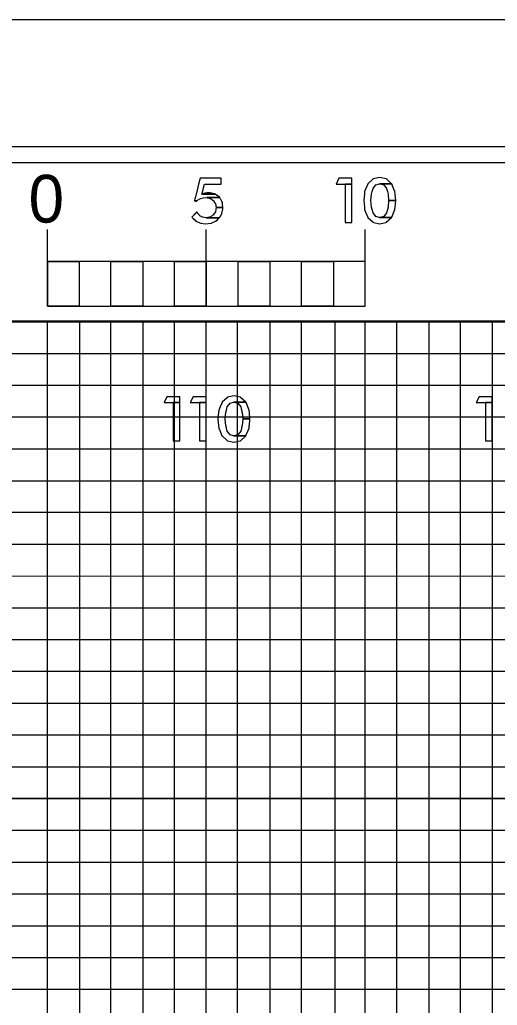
# Model space of a CAD drawing. Extents: x -13 to 323, y -5 to 1431.
# Drawn here: x 264.13 to 279.16, y 1283.5 to 1314.5 of the extents above; entities that cross this region are included whole.
import ezdxf

# ---------------------------------------------------------------- set-up
doc = ezdxf.new("R2010")
doc.units = 0
for name, color, linetype in [('Prop XS Bar Scale Labels', 7, 'Continuous'), ('Prop XS Offset Labels', 7, 'Continuous'), ('Sheet Cross Section CELL', 7, 'Continuous'), ('Sheet Cross Section Grid Major CELL', 7, 'Continuous'), ('Sheet Cross Section Grid Middle CELL', 7, 'Continuous'), ('Sheet Cross Section Grid Minor 1 CELL', 7, 'Continuous'), ('Sheet Cross Section Grid Minor 2 CELL', 7, 'Continuous'), ('Sheet Cross Section Scale CELL', 7, 'Continuous'), ('Sheet Cutting Line CELL', 7, 'Continuous'), ('Sheet DOT Grid CELL', 7, 'Continuous'), ('Sheet Plot Border Inside CELL', 7, 'Continuous'), ('Sheet Plot Border Outside CELL', 7, 'Continuous')]:
    doc.layers.add(name, color=color, linetype=linetype)

msp = doc.modelspace()

# ---------------------------------------------------------------- linework, layer by layer
at = {"layer": 'Prop XS Bar Scale Labels'}
for points in [[(269.63, 1308.81), (269.627, 1308.798), (269.698, 1308.798), (269.711, 1308.81), (269.727, 1308.824), (269.798, 1308.867), (269.83, 1308.877), (269.9, 1308.899), (270.014, 1308.905), (270.422, 1308.905), (270.414, 1308.92), (270.28, 1309.015), (269.858, 1309.015), (269.861, 1309.028), (269.861, 1309.028), (269.866, 1309.048), (269.941, 1309.326), (270.466, 1309.326), (270.466, 1309.511), (269.803, 1309.511), (269.757, 1309.326), (269.689, 1309.048), (269.684, 1309.028), (269.681, 1309.015), (269.658, 1308.92), (269.654, 1308.905), (269.652, 1308.899), (269.647, 1308.877), (269.644, 1308.867), (269.634, 1308.824)], [(274.174, 1309.511), (274.085, 1309.329), (274.583, 1309.329), (274.583, 1309.511)], [(275.258, 1308.125), (275.457, 1308.084), (275.652, 1308.125), (275.663, 1308.127), (275.828, 1308.279), (275.454, 1308.279), (275.445, 1308.281), (275.44, 1308.283), (275.335, 1308.312), (275.248, 1308.425), (275.248, 1308.426), (275.248, 1308.426), (275.22, 1308.527), (275.22, 1308.529), (275.2, 1308.602), (275.198, 1308.606), (275.181, 1308.809), (275.181, 1308.811), (275.181, 1308.813), (275.198, 1309.015), (275.219, 1309.092), (275.22, 1309.094), (275.246, 1309.192), (275.247, 1309.195), (275.335, 1309.31), (275.448, 1309.339), (275.452, 1309.34), (275.462, 1309.343), (275.832, 1309.343), (275.669, 1309.492), (275.66, 1309.494), (275.46, 1309.538), (275.46, 1309.538), (275.252, 1309.494), (275.25, 1309.492), (275.088, 1309.343), (275.085, 1309.34), (275.084, 1309.339), (275.072, 1309.31), (275.025, 1309.195), (275.024, 1309.192), (274.983, 1309.094), (274.983, 1309.092), (274.975, 1309.015), (274.954, 1308.813), (274.953, 1308.811), (274.954, 1308.809), (274.974, 1308.606), (274.974, 1308.602), (274.982, 1308.529), (274.982, 1308.527), (275.023, 1308.426), (275.024, 1308.425), (275.07, 1308.312), (275.082, 1308.283), (275.082, 1308.281), (275.085, 1308.279), (275.255, 1308.127)], [(274.374, 1309.329), (274.374, 1308.12), (274.583, 1308.12), (274.583, 1309.329)], [(275.719, 1309.015), (275.735, 1308.813), (275.962, 1308.813), (275.942, 1309.015), (275.935, 1309.092), (275.934, 1309.094), (275.934, 1309.094), (275.895, 1309.192), (275.895, 1309.192), (275.893, 1309.195), (275.848, 1309.31), (275.847, 1309.31), (275.835, 1309.339), (275.835, 1309.34), (275.832, 1309.343), (275.462, 1309.343), (275.472, 1309.34), (275.475, 1309.339), (275.582, 1309.31), (275.669, 1309.195), (275.672, 1309.192), (275.698, 1309.094), (275.698, 1309.092)], [(269.895, 1309.028), (269.858, 1309.015), (270.28, 1309.015), (270.262, 1309.028), (270.164, 1309.048), (269.953, 1309.048)], [(270.091, 1309.062), (269.953, 1309.048), (270.164, 1309.048), (270.091, 1309.062)], [(270.286, 1308.711), (270.308, 1308.591), (270.521, 1308.591), (270.51, 1308.711), (270.51, 1308.711), (270.507, 1308.751), (270.487, 1308.786), (270.481, 1308.798), (270.475, 1308.81), (270.467, 1308.824), (270.443, 1308.867), (270.438, 1308.877), (270.426, 1308.899), (270.422, 1308.905), (270.014, 1308.905), (270.041, 1308.899), (270.132, 1308.877), (270.146, 1308.867), (270.206, 1308.824), (270.227, 1308.81), (270.234, 1308.798), (270.241, 1308.786), (270.262, 1308.751)], [(269.627, 1308.798), (269.685, 1308.786), (269.698, 1308.798)], [(270.103, 1308.288), (269.996, 1308.269), (270.408, 1308.269), (270.423, 1308.288), (270.424, 1308.289), (270.425, 1308.29), (270.425, 1308.29), (270.462, 1308.336), (270.471, 1308.347), (270.473, 1308.353), (270.487, 1308.405), (270.502, 1308.46), (270.525, 1308.544), (270.521, 1308.591), (270.308, 1308.591), (270.3, 1308.544), (270.286, 1308.46), (270.25, 1308.405), (270.217, 1308.353), (270.207, 1308.347), (270.19, 1308.336), (270.116, 1308.29), (270.108, 1308.289)], [(275.465, 1308.281), (275.454, 1308.279), (275.828, 1308.279), (275.831, 1308.281), (275.833, 1308.283), (275.845, 1308.312), (275.892, 1308.425), (275.892, 1308.426), (275.934, 1308.527), (275.935, 1308.529), (275.942, 1308.602), (275.942, 1308.606), (275.962, 1308.809), (275.963, 1308.811), (275.962, 1308.813), (275.735, 1308.813), (275.735, 1308.811), (275.735, 1308.809), (275.719, 1308.606), (275.718, 1308.602), (275.699, 1308.529), (275.698, 1308.527), (275.671, 1308.426), (275.67, 1308.425), (275.582, 1308.312), (275.47, 1308.283)], [(269.829, 1308.103), (269.965, 1308.084), (270.163, 1308.103), (270.171, 1308.107), (270.294, 1308.167), (270.294, 1308.167), (270.344, 1308.191), (270.388, 1308.245), (270.408, 1308.269), (269.996, 1308.269), (269.887, 1308.288), (269.885, 1308.289), (269.882, 1308.29), (269.799, 1308.336), (269.789, 1308.347), (269.783, 1308.353), (269.783, 1308.353), (269.733, 1308.405), (269.7, 1308.455), (269.7, 1308.455), (269.655, 1308.405), (269.608, 1308.353), (269.602, 1308.347), (269.593, 1308.336), (269.551, 1308.29), (269.55, 1308.289), (269.551, 1308.288), (269.566, 1308.269), (269.585, 1308.245), (269.649, 1308.191), (269.677, 1308.167), (269.801, 1308.107)]]:
    msp.add_lwpolyline(points, close=True, dxfattribs=at)
at = {"layer": 'Prop XS Offset Labels'}
for points in [[(268.76, 1302.641), (268.671, 1302.459), (269.17, 1302.459), (269.17, 1302.641)], [(269.587, 1302.641), (269.498, 1302.459), (269.997, 1302.459), (269.997, 1302.641)], [(270.672, 1301.255), (270.871, 1301.214), (271.066, 1301.255), (271.077, 1301.257), (271.242, 1301.409), (270.868, 1301.409), (270.858, 1301.411), (270.853, 1301.413), (270.749, 1301.442), (270.662, 1301.555), (270.661, 1301.556), (270.661, 1301.556), (270.634, 1301.657), (270.633, 1301.659), (270.613, 1301.732), (270.612, 1301.736), (270.594, 1301.939), (270.594, 1301.941), (270.595, 1301.943), (270.612, 1302.145), (270.633, 1302.222), (270.633, 1302.224), (270.66, 1302.322), (270.661, 1302.325), (270.749, 1302.44), (270.862, 1302.469), (270.865, 1302.47), (270.876, 1302.473), (271.246, 1302.473), (271.082, 1302.622), (271.074, 1302.624), (270.873, 1302.668), (270.873, 1302.668), (270.665, 1302.624), (270.663, 1302.622), (270.502, 1302.473), (270.499, 1302.47), (270.498, 1302.469), (270.486, 1302.44), (270.439, 1302.325), (270.437, 1302.322), (270.397, 1302.224), (270.397, 1302.222), (270.389, 1302.145), (270.367, 1301.943), (270.367, 1301.941), (270.367, 1301.939), (270.387, 1301.736), (270.388, 1301.732), (270.395, 1301.659), (270.396, 1301.657), (270.437, 1301.556), (270.437, 1301.555), (270.483, 1301.442), (270.495, 1301.413), (270.496, 1301.411), (270.499, 1301.409), (270.669, 1301.257)], [(278.581, 1302.641), (278.492, 1302.459), (278.99, 1302.459), (278.99, 1302.641)], [(268.961, 1302.459), (268.961, 1301.25), (269.17, 1301.25), (269.17, 1302.459)], [(269.788, 1302.459), (269.788, 1301.25), (269.997, 1301.25), (269.997, 1302.459)], [(271.132, 1302.145), (271.149, 1301.943), (271.376, 1301.943), (271.356, 1302.145), (271.349, 1302.222), (271.348, 1302.224), (271.348, 1302.224), (271.308, 1302.322), (271.308, 1302.322), (271.307, 1302.325), (271.261, 1302.44), (271.261, 1302.44), (271.249, 1302.469), (271.249, 1302.47), (271.246, 1302.473), (270.876, 1302.473), (270.885, 1302.47), (270.889, 1302.469), (270.995, 1302.44), (271.083, 1302.325), (271.085, 1302.322), (271.111, 1302.224), (271.112, 1302.222)], [(278.781, 1302.459), (278.781, 1301.25), (278.99, 1301.25), (278.99, 1302.459)], [(270.878, 1301.411), (270.868, 1301.409), (271.242, 1301.409), (271.245, 1301.411), (271.247, 1301.413), (271.259, 1301.442), (271.305, 1301.555), (271.306, 1301.556), (271.348, 1301.657), (271.348, 1301.659), (271.355, 1301.732), (271.356, 1301.736), (271.376, 1301.939), (271.376, 1301.941), (271.376, 1301.943), (271.149, 1301.943), (271.149, 1301.941), (271.148, 1301.939), (271.132, 1301.736), (271.132, 1301.732), (271.112, 1301.659), (271.112, 1301.657), (271.085, 1301.556), (271.084, 1301.555), (270.995, 1301.442), (270.883, 1301.413)]]:
    msp.add_lwpolyline(points, close=True, dxfattribs=at)
at = {"layer": 'Sheet Cross Section CELL'}
for points in [[(320, 1310), (0, 1310), (0, 1100), (320, 1100)], [(280, 1310), (260, 1310), (260, 1305.03), (280, 1305.03)]]:
    msp.add_lwpolyline(points, close=True, dxfattribs=at)
at = {"layer": 'Sheet Cross Section Grid Major CELL'}
msp.add_line((270, 1100), (270, 1305), dxfattribs=at)
msp.add_lwpolyline([(0, 1300), (320, 1300), (320, 1290), (0, 1290)], dxfattribs=at)
at = {"layer": 'Sheet Cross Section Grid Middle CELL'}
for points in [[(255, 1100), (255, 1310), (259.93, 1310), (260, 1310), (260, 1305), (264.99, 1305), (264.99, 1100)], [(0, 1305), (275, 1305)], [(275, 1100), (275, 1305), (285, 1305), (285, 1100)], [(0, 1285), (320, 1285), (320, 1295), (0, 1295)]]:
    msp.add_lwpolyline(points, dxfattribs=at)
at = {"layer": 'Sheet Cross Section Grid Minor 1 CELL'}
msp.add_line((0, 1304), (320, 1304), dxfattribs=at)
for points in [[(0, 1303), (270, 1303), (320, 1303), (320, 1302), (0, 1302)], [(0, 1301), (320, 1301), (320, 1299), (0, 1299)], [(0, 1298), (320, 1298), (320, 1297), (0, 1296.98)], [(0, 1296), (320, 1296), (320, 1294), (0, 1294)], [(0, 1293), (320, 1293), (320, 1292), (0, 1292)], [(0, 1291), (320, 1291), (320, 1289), (0, 1289)], [(0, 1288), (320, 1288), (320, 1287), (0, 1287)], [(0, 1286), (320, 1286), (320, 1284), (0, 1284)]]:
    msp.add_lwpolyline(points, dxfattribs=at)
at = {"layer": 'Sheet Cross Section Grid Minor 2 CELL'}
for p, q in [((267, 1305), (266.01, 1305)), ((266.01, 1305), (266.01, 1100)), ((267, 1100), (267, 1305)), ((269, 1305), (268, 1305)), ((268, 1305), (268, 1100)), ((269, 1100), (269, 1305))]:
    msp.add_line(p, q, dxfattribs=at)
for points in [[(270, 1100), (270.98, 1100), (270.98, 1305), (272, 1305), (272, 1100)], [(272, 1100), (273, 1100), (273, 1305), (274.05, 1305), (274.05, 1100)], [(275, 1100), (276, 1100), (276, 1305), (277, 1305), (277, 1100)], [(277, 1100), (278, 1100), (278, 1305), (279, 1305), (279, 1100)]]:
    msp.add_lwpolyline(points, dxfattribs=at)
at = {"layer": 'Sheet Cross Section Scale CELL'}
for p, q in [((265, 1305.49), (265, 1307.9)), ((265, 1306.9), (265, 1307.9)), ((270, 1305.49), (270, 1307.9)), ((275, 1305.49), (275, 1307.9)), ((275, 1306.9), (275, 1307.9))]:
    msp.add_line(p, q, dxfattribs=at)
for points in [[(275, 1306.9), (265, 1306.9), (265, 1305.49), (275, 1305.49)], [(265, 1306.9), (266, 1306.9), (266, 1305.49), (265, 1305.49)], [(267, 1306.9), (268, 1306.9), (268, 1305.49), (267, 1305.49)], [(269, 1306.9), (270, 1306.9), (270, 1305.49), (269, 1305.49)], [(271, 1306.9), (272, 1306.9), (272, 1305.49), (271, 1305.49)], [(273, 1306.9), (274, 1306.9), (274, 1305.49), (273, 1305.49)]]:
    msp.add_lwpolyline(points, close=True, dxfattribs=at)
at = {"layer": 'Sheet Cutting Line CELL'}
msp.add_line((323.3, 1314.5), (-13.4, 1314.5), dxfattribs=at)
at = {"layer": 'Sheet DOT Grid CELL'}
for p, q in [((270, 1100), (270, 1304.687)), ((0, 1300), (320, 1300)), ((0, 1290), (320, 1290))]:
    msp.add_line(p, q, dxfattribs=at)
at = {"layer": 'Sheet Plot Border Inside CELL'}
msp.add_lwpolyline([(-10.8, 1099.5), (322.4, 1099.5), (322.4, 1310.5), (-10.8, 1310.5)], close=True, dxfattribs=at)
at = {"layer": 'Sheet Plot Border Outside CELL'}
msp.add_lwpolyline([(-13.4, 1095.5), (323.3, 1095.5), (323.3, 1314.5), (-13.4, 1314.5)], close=True, dxfattribs=at)

# ---------------------------------------------------------------- texts
at = {"layer": 'Sheet Cross Section Scale CELL'}
msp.add_text('0', height=1.5, dxfattribs=at).set_placement((264.41, 1308.12))

doc.saveas('drawing.dxf')
